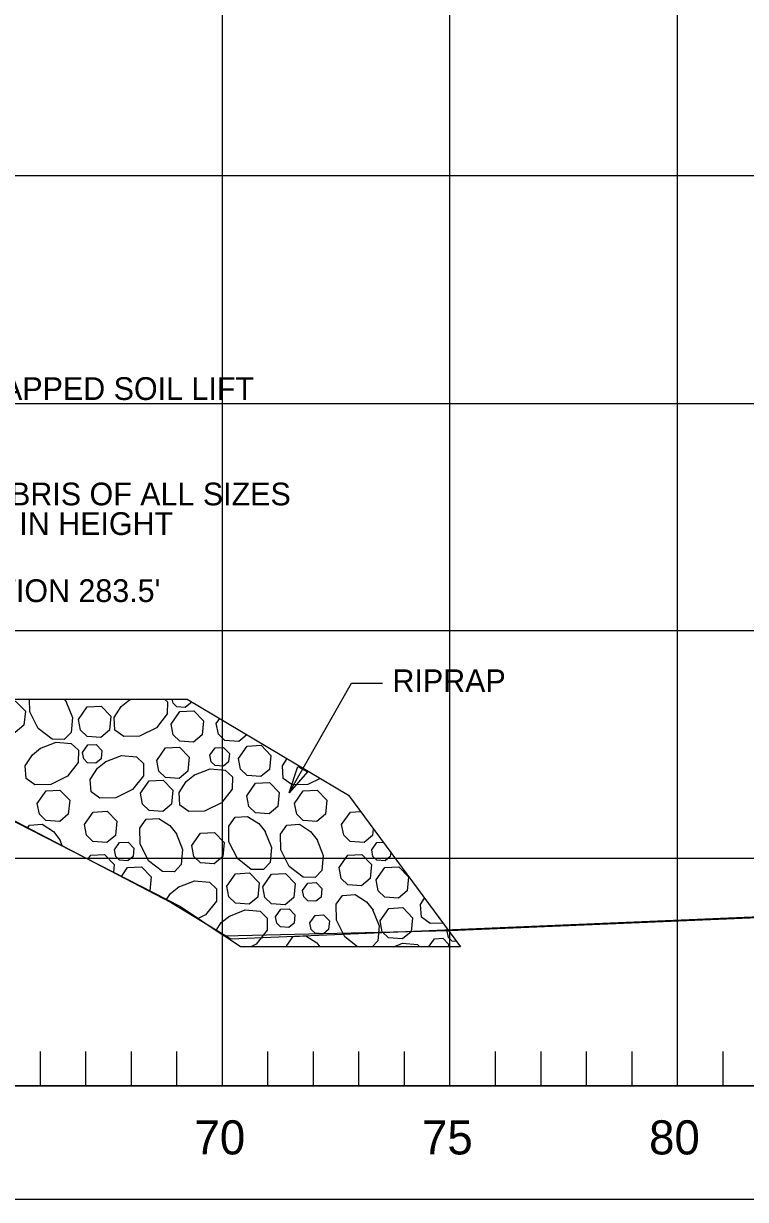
# Model space of a CAD drawing. Extents: x 1578769 to 1579225, y 724002 to 724828.
# Drawn here: x 1578893.4 to 1578909.27, y 724524.48 to 724550.33 of the extents above; entities that cross this region are included whole.
import ezdxf

# ---------------------------------------------------------------- set-up
doc = ezdxf.new("R2010")
doc.units = 0
for name, color, linetype in [('1', 7, 'Continuous'), ('Default', 7, 'Continuous'), ('Old_Level_1', 7, 'Continuous'), ('Old_Level_41', 7, 'Continuous'), ('Old_Level_42', 7, 'Continuous'), ('R_Exist Surface', 7, 'Continuous'), ('R_Rip-Rap', 7, 'Continuous')]:
    doc.layers.add(name, color=color, linetype=linetype)

msp = doc.modelspace()

# ---------------------------------------------------------------- linework, layer by layer
at = {"layer": '1'}
msp.add_lwpolyline([(1578899.238, 724533.415), (1578900.607, 724535.828), (1578901.292, 724535.828)], dxfattribs=at)
msp.add_lwpolyline([(1578899.639, 724533.877), (1578899.238, 724533.415), (1578899.43, 724533.996)], close=True, dxfattribs=at)
at = {"layer": 'Default'}
msp.add_line((1578827.766, 724526.976), (1579127.766, 724526.976), dxfattribs=at)
msp.add_lwpolyline([(1578827.766, 724545.778), (1578841.746, 724545.874), (1578855.126, 724545.979), (1578880.286, 724546.165), (1578882.476, 724543.201), (1578888.466, 724535.266), (1578896.646, 724531.004), (1578897.956, 724530.207), (1578900.066, 724530.294), (1578933.126, 724531.692), (1578958.306, 724535.052), (1578969.886, 724536.54), (1578983.926, 724537.607), (1579000.856, 724538.888), (1579028.426, 724540.267), (1579057.456, 724541.791), (1579058.756, 724541.812)], dxfattribs=at)
at = {"layer": 'Old_Level_1'}
for points in [[(1578822.766, 724559.476), (1578930.266, 724559.476), (1578930.266, 724524.476), (1578822.766, 724524.476)], [(1578827.766, 724556.976), (1578927.766, 724556.976), (1578927.766, 724526.976), (1578827.766, 724526.976)]]:
    msp.add_lwpolyline(points, close=True, dxfattribs=at)
at = {"layer": 'Old_Level_41'}
for p, q in [((1578897.766, 724556.976), (1578897.766, 724526.976)), ((1578902.766, 724526.976), (1578902.766, 724556.976)), ((1578907.766, 724556.976), (1578907.766, 724526.976))]:
    msp.add_line(p, q, dxfattribs=at)
for points in [[(1578927.766, 724546.976), (1578827.766, 724546.976)], [(1578888.475, 724541.976), (1578927.766, 724541.976)], [(1578927.766, 724536.976), (1578827.766, 724536.976)], [(1578827.766, 724531.976), (1578927.766, 724531.976)]]:
    msp.add_lwpolyline(points, dxfattribs=at)
at = {"layer": 'Old_Level_42'}
for p, q in [((1578893.766, 724527.726), (1578893.766, 724526.976)), ((1578894.766, 724527.726), (1578894.766, 724526.976)), ((1578895.766, 724527.726), (1578895.766, 724526.976)), ((1578896.766, 724527.726), (1578896.766, 724526.976)), ((1578898.766, 724527.726), (1578898.766, 724526.976)), ((1578899.766, 724527.726), (1578899.766, 724526.976)), ((1578900.766, 724527.726), (1578900.766, 724526.976)), ((1578901.766, 724527.726), (1578901.766, 724526.976)), ((1578903.766, 724527.726), (1578903.766, 724526.976)), ((1578904.766, 724527.726), (1578904.766, 724526.976)), ((1578905.766, 724527.726), (1578905.766, 724526.976)), ((1578906.766, 724527.726), (1578906.766, 724526.976)), ((1578908.766, 724527.726), (1578908.766, 724526.976))]:
    msp.add_line(p, q, dxfattribs=at)
at = {"layer": 'R_Exist Surface'}
msp.add_lwpolyline([(1578827.766, 724545.753), (1578832.87, 724545.829), (1578835.855, 724545.829), (1578849.85, 724545.921), (1578865.935, 724546.072), (1578876.895, 724546.144), (1578879.811, 724546.167), (1578880.852, 724545.469), (1578882.795, 724542.798), (1578885.883, 724538.793), (1578888.763, 724535.059), (1578896.849, 724530.913), (1578897.81, 724530.272), (1578902.771, 724530.386), (1578927.766, 724531.445)], dxfattribs=at)
at = {"layer": 'R_Rip-Rap'}
for p, q in [((1578883.887, 724535.476), (1578896.998, 724535.476)), ((1578894.295, 724535.476), (1578894.341, 724535.418)), ((1578895.716, 724535.451), (1578895.78, 724535.476)), ((1578896.998, 724535.476), (1578900.542, 724533.362)), ((1578897.638, 724534.939), (1578897.715, 724535.048)), ((1578900.542, 724533.362), (1578903.001, 724530.032)), ((1578894.193, 724532.399), (1578894.254, 724532.243)), ((1578898.17, 724530.032), (1578897.81, 724530.272)), ((1578902.71, 724530.376), (1578902.727, 724530.402)), ((1578903.001, 724530.032), (1578898.17, 724530.032)), ((1578902.316, 724530.032), (1578902.313, 724530.043))]:
    msp.add_line(p, q, dxfattribs=at)
for points in [[(1578892.73, 724535.14), (1578892.922, 724535.413), (1578893.228, 724535.431), (1578893.442, 724535.209), (1578893.411, 724534.9), (1578893.221, 724534.742), (1578892.918, 724534.764), (1578892.776, 724534.902), (1578892.73, 724535.14)], [(1578894.332, 724535.432), (1578894.475, 724535.073), (1578894.446, 724534.743), (1578894.297, 724534.586), (1578894.029, 724534.591), (1578893.725, 724534.829), (1578893.541, 724535.197), (1578893.536, 724535.476)], [(1578896.499, 724535.476), (1578896.563, 724535.415), (1578896.558, 724535.148), (1578896.32, 724534.843), (1578895.952, 724534.659), (1578895.605, 724534.653), (1578895.41, 724534.792), (1578895.391, 724535.068), (1578895.55, 724535.315), (1578895.731, 724535.46)], [(1578897.073, 724535.431), (1578897.069, 724535.385), (1578896.955, 724535.29), (1578896.773, 724535.303), (1578896.688, 724535.386), (1578896.67, 724535.476)], [(1578894.609, 724535.029), (1578894.801, 724535.303), (1578895.108, 724535.32), (1578895.321, 724535.099), (1578895.29, 724534.789), (1578895.1, 724534.632), (1578894.798, 724534.654), (1578894.655, 724534.792), (1578894.609, 724535.029)], [(1578896.647, 724534.928), (1578896.839, 724535.201), (1578897.146, 724535.219), (1578897.359, 724534.998), (1578897.328, 724534.688), (1578897.139, 724534.53), (1578896.836, 724534.552), (1578896.693, 724534.691), (1578896.647, 724534.928)], [(1578898.311, 724534.693), (1578898.13, 724534.542), (1578897.827, 724534.564), (1578897.684, 724534.702), (1578897.638, 724534.939)], [(1578893.762, 724534.388), (1578894.122, 724534.53), (1578894.452, 724534.502), (1578894.609, 724534.353), (1578894.604, 724534.085), (1578894.366, 724533.781), (1578893.998, 724533.597), (1578893.651, 724533.591), (1578893.456, 724533.729), (1578893.437, 724534.005), (1578893.596, 724534.253), (1578893.777, 724534.397)], [(1578894.696, 724534.303), (1578894.812, 724534.467), (1578894.996, 724534.478), (1578895.123, 724534.345), (1578895.105, 724534.159), (1578894.991, 724534.065), (1578894.81, 724534.078), (1578894.724, 724534.161), (1578894.696, 724534.303)], [(1578896.332, 724534.128), (1578896.524, 724534.401), (1578896.831, 724534.419), (1578897.044, 724534.198), (1578897.013, 724533.888), (1578896.824, 724533.73), (1578896.521, 724533.752), (1578896.378, 724533.891), (1578896.332, 724534.128)], [(1578897.497, 724534.24), (1578897.613, 724534.404), (1578897.797, 724534.415), (1578897.925, 724534.282), (1578897.906, 724534.096), (1578897.793, 724534.002), (1578897.611, 724534.015), (1578897.525, 724534.098), (1578897.498, 724534.24)], [(1578898.127, 724534.17), (1578898.319, 724534.443), (1578898.626, 724534.46), (1578898.839, 724534.239), (1578898.808, 724533.93), (1578898.619, 724533.772), (1578898.316, 724533.794), (1578898.173, 724533.932), (1578898.127, 724534.17)], [(1578895.194, 724534.093), (1578895.553, 724534.235), (1578895.883, 724534.207), (1578896.04, 724534.058), (1578896.035, 724533.79), (1578895.797, 724533.486), (1578895.429, 724533.302), (1578895.082, 724533.296), (1578894.887, 724533.434), (1578894.869, 724533.71), (1578895.027, 724533.958), (1578895.209, 724534.102)], [(1578899.922, 724533.732), (1578899.651, 724533.597), (1578899.304, 724533.591), (1578899.109, 724533.729), (1578899.091, 724534.005), (1578899.194, 724534.166)], [(1578897.146, 724533.803), (1578897.505, 724533.945), (1578897.836, 724533.916), (1578897.992, 724533.767), (1578897.987, 724533.499), (1578897.749, 724533.195), (1578897.381, 724533.011), (1578897.035, 724533.005), (1578896.839, 724533.144), (1578896.821, 724533.42), (1578896.979, 724533.667), (1578897.161, 724533.812)], [(1578895.971, 724533.405), (1578896.163, 724533.678), (1578896.469, 724533.696), (1578896.683, 724533.475), (1578896.652, 724533.165), (1578896.462, 724533.008), (1578896.159, 724533.03), (1578896.017, 724533.168), (1578895.971, 724533.405)], [(1578898.308, 724533.352), (1578898.5, 724533.625), (1578898.806, 724533.642), (1578899.02, 724533.421), (1578898.989, 724533.112), (1578898.799, 724532.954), (1578898.497, 724532.976), (1578898.354, 724533.114), (1578898.308, 724533.352)], [(1578893.704, 724533.184), (1578893.896, 724533.457), (1578894.203, 724533.475), (1578894.416, 724533.254), (1578894.385, 724532.944), (1578894.196, 724532.787), (1578893.893, 724532.809), (1578893.751, 724532.947), (1578893.705, 724533.184)], [(1578899.358, 724533.184), (1578899.55, 724533.457), (1578899.857, 724533.475), (1578900.07, 724533.254), (1578900.039, 724532.944), (1578899.849, 724532.787), (1578899.547, 724532.809), (1578899.404, 724532.947), (1578899.358, 724533.184)], [(1578894.739, 724532.72), (1578894.931, 724532.993), (1578895.238, 724533.01), (1578895.451, 724532.789), (1578895.42, 724532.48), (1578895.231, 724532.322), (1578894.928, 724532.344), (1578894.785, 724532.482), (1578894.739, 724532.72)], [(1578896.755, 724532.527), (1578896.898, 724532.167), (1578896.869, 724531.837), (1578896.72, 724531.68), (1578896.452, 724531.685), (1578896.148, 724531.923), (1578895.964, 724532.291), (1578895.958, 724532.638), (1578896.096, 724532.833), (1578896.373, 724532.852), (1578896.62, 724532.694), (1578896.764, 724532.512)], [(1578898.707, 724532.573), (1578898.85, 724532.214), (1578898.821, 724531.884), (1578898.672, 724531.727), (1578898.404, 724531.732), (1578898.1, 724531.97), (1578897.916, 724532.338), (1578897.91, 724532.685), (1578898.049, 724532.88), (1578898.325, 724532.898), (1578898.572, 724532.74), (1578898.717, 724532.559)], [(1578900.392, 724532.72), (1578900.584, 724532.993), (1578900.805, 724533.005)], [(1578893.486, 724532.637), (1578893.534, 724532.706), (1578893.81, 724532.724), (1578894.057, 724532.566), (1578894.202, 724532.384)], [(1578897.1, 724532.255), (1578897.292, 724532.528), (1578897.599, 724532.546), (1578897.812, 724532.325), (1578897.781, 724532.015), (1578897.592, 724531.857), (1578897.289, 724531.879), (1578897.147, 724532.017), (1578897.1, 724532.255)], [(1578899.846, 724532.399), (1578899.989, 724532.04), (1578899.96, 724531.709), (1578899.811, 724531.553), (1578899.543, 724531.558), (1578899.239, 724531.796), (1578899.055, 724532.164), (1578899.049, 724532.51), (1578899.187, 724532.706), (1578899.464, 724532.724), (1578899.711, 724532.566), (1578899.855, 724532.384)], [(1578901.088, 724532.623), (1578901.073, 724532.48), (1578900.884, 724532.322), (1578900.581, 724532.344), (1578900.439, 724532.482), (1578900.392, 724532.72)], [(1578895.399, 724532.16), (1578895.514, 724532.324), (1578895.698, 724532.334), (1578895.826, 724532.202), (1578895.808, 724532.016), (1578895.694, 724531.921), (1578895.512, 724531.934), (1578895.427, 724532.017), (1578895.399, 724532.16)], [(1578901.052, 724532.16), (1578901.168, 724532.324), (1578901.303, 724532.331)], [(1578894.815, 724531.956), (1578894.877, 724532.044), (1578895.184, 724532.062), (1578895.397, 724531.841), (1578895.38, 724531.666)], [(1578900.339, 724531.771), (1578900.531, 724532.044), (1578900.837, 724532.062), (1578901.05, 724531.841), (1578901.02, 724531.531), (1578900.83, 724531.373), (1578900.527, 724531.395), (1578900.385, 724531.533), (1578900.339, 724531.771)], [(1578901.47, 724532.105), (1578901.461, 724532.016), (1578901.347, 724531.921), (1578901.166, 724531.934), (1578901.08, 724532.017), (1578901.052, 724532.16)], [(1578895.552, 724531.578), (1578895.689, 724531.773), (1578895.995, 724531.79), (1578896.209, 724531.569), (1578896.178, 724531.259), (1578896.176, 724531.258)], [(1578901.15, 724531.5), (1578901.342, 724531.773), (1578901.649, 724531.79), (1578901.862, 724531.569), (1578901.831, 724531.259), (1578901.642, 724531.102), (1578901.339, 724531.124), (1578901.197, 724531.262), (1578901.15, 724531.499)], [(1578897.869, 724531.364), (1578898.061, 724531.637), (1578898.368, 724531.655), (1578898.581, 724531.434), (1578898.55, 724531.124), (1578898.361, 724530.967), (1578898.058, 724530.988), (1578897.915, 724531.127), (1578897.869, 724531.364)], [(1578898.659, 724531.352), (1578898.851, 724531.626), (1578899.158, 724531.643), (1578899.371, 724531.422), (1578899.34, 724531.112), (1578899.151, 724530.955), (1578898.848, 724530.977), (1578898.706, 724531.115), (1578898.659, 724531.352)], [(1578896.544, 724531.069), (1578896.631, 724531.204), (1578896.812, 724531.348)], [(1578896.798, 724531.339), (1578897.157, 724531.482), (1578897.487, 724531.453), (1578897.644, 724531.304), (1578897.639, 724531.036), (1578897.401, 724530.732), (1578897.241, 724530.652)], [(1578899.533, 724531.268), (1578899.648, 724531.432), (1578899.832, 724531.443), (1578899.96, 724531.31), (1578899.942, 724531.124), (1578899.828, 724531.03), (1578899.646, 724531.043), (1578899.561, 724531.126), (1578899.533, 724531.268)], [(1578900.744, 724530.032), (1578900.465, 724530.25), (1578900.281, 724530.618), (1578900.275, 724530.965), (1578900.414, 724531.16), (1578900.69, 724531.179), (1578900.937, 724531.02), (1578901.082, 724530.839)], [(1578902.621, 724530.547), (1578902.339, 724530.542), (1578902.144, 724530.68), (1578902.126, 724530.957), (1578902.215, 724531.096)], [(1578897.912, 724530.697), (1578898.272, 724530.84), (1578898.602, 724530.811), (1578898.759, 724530.662), (1578898.754, 724530.394), (1578898.516, 724530.09), (1578898.4, 724530.032)], [(1578898.939, 724530.692), (1578899.054, 724530.856), (1578899.238, 724530.866), (1578899.366, 724530.733), (1578899.347, 724530.548), (1578899.234, 724530.453), (1578899.052, 724530.466), (1578898.966, 724530.549), (1578898.939, 724530.692)], [(1578899.695, 724530.557), (1578899.81, 724530.72), (1578899.994, 724530.731), (1578900.122, 724530.598), (1578900.104, 724530.413), (1578899.99, 724530.318), (1578899.809, 724530.331), (1578899.723, 724530.414), (1578899.695, 724530.556)], [(1578901.072, 724530.853), (1578901.215, 724530.494), (1578901.186, 724530.164), (1578901.061, 724530.032)], [(1578901.236, 724530.601), (1578901.428, 724530.874), (1578901.734, 724530.891), (1578901.948, 724530.67), (1578901.917, 724530.361), (1578901.727, 724530.203), (1578901.424, 724530.225), (1578901.282, 724530.363), (1578901.236, 724530.601)], [(1578897.635, 724530.389), (1578897.745, 724530.562), (1578897.927, 724530.706)], [(1578899.188, 724530.032), (1578899.188, 724530.059), (1578899.327, 724530.254), (1578899.603, 724530.272), (1578899.85, 724530.114), (1578899.916, 724530.032)], [(1578902.313, 724530.043), (1578902.429, 724530.207), (1578902.613, 724530.218), (1578902.74, 724530.085), (1578902.735, 724530.032)], [(1578902.918, 724530.144), (1578902.823, 724530.151), (1578902.737, 724530.234), (1578902.71, 724530.376)], [(1578901.538, 724530.032), (1578901.729, 724530.108), (1578902.059, 724530.079), (1578902.109, 724530.032)]]:
    msp.add_lwpolyline(points, dxfattribs=at)

# ---------------------------------------------------------------- texts
at = {"layer": '1'}
for s, height, p in [("1' COIR WRAPPED SOIL LIFT", 0.5, (1578889.273, 724542.051)), ('WOODY DEBRIS OF ALL SIZES', 0.5, (1578889.391, 724539.734)), ("IN LAYER 3' IN HEIGHT", 0.5, (1578889.391, 724539.083)), ("ELEVATION 283.5'", 0.5, (1578890.67, 724537.609)), ('RIPRAP', 0.5, (1578901.509, 724535.628)), ('70', 0.75, (1578897.158, 724525.466)), ('75', 0.75, (1578902.158, 724525.466)), ('80', 0.75, (1578907.147, 724525.466))]:
    msp.add_text(s, height=height, dxfattribs=at).set_placement(p)

doc.saveas('drawing.dxf')
